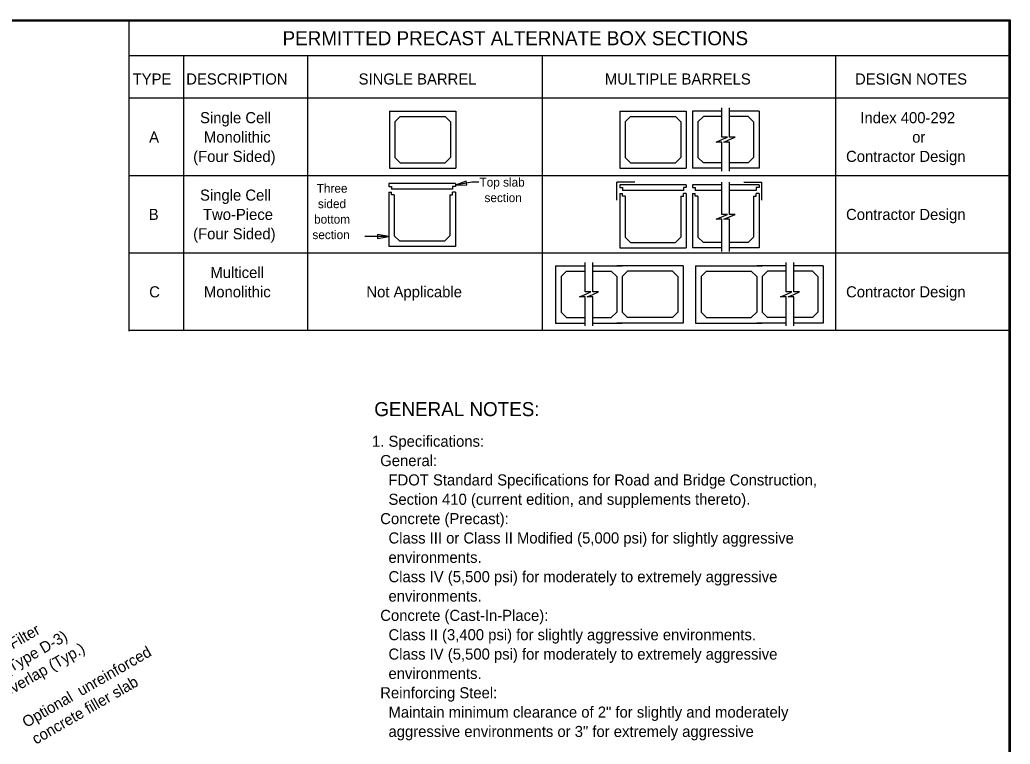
# Model space of a CAD drawing. Extents: x 0 to 123, y 0 to 78.
# Drawn here: x 69.2 to 123.2, y 38.4 to 77.9 of the extents above; entities that cross this region are included whole.
import ezdxf

# ---------------------------------------------------------------- set-up
doc = ezdxf.new("R2010")
doc.units = 0
for name, color, linetype in [('Dimension', 7, 'Continuous'), ('Miscellaneous', 7, 'Continuous'), ('Miscellaneous1', 7, 'Continuous'), ('Patterning', 7, 'Continuous'), ('SubStrConc', 7, 'Continuous'), ('TextStructures', 7, 'Continuous')]:
    doc.layers.add(name, color=color, linetype=linetype)

msp = doc.modelspace()

# ---------------------------------------------------------------- linework, layer by layer
at = {"layer": 'Dimension'}
for p, q in [((75.125, 77.856), (123.127, 77.856)), ((75.125, 77.856), (75.125, 60.919)), ((123.127, 77.856), (123.127, 60.97)), ((75.125, 75.954), (123.127, 75.954)), ((78.093, 75.954), (78.093, 60.97)), ((84.866, 75.954), (84.866, 60.97)), ((97.659, 75.954), (97.659, 60.97)), ((113.661, 75.954), (113.661, 60.97)), ((75.125, 73.642), (123.127, 73.642)), ((75.125, 69.418), (123.127, 69.418)), ((93.838, 69.053), (92.931, 68.893)), ((94.208, 69.053), (93.838, 69.053)), ((89.303, 66.08), (87.985, 66.08)), ((75.125, 65.194), (123.127, 65.194)), ((75.125, 60.97), (123.127, 60.97))]:
    msp.add_line(p, q, dxfattribs=at)
for points in [[(107.476, 69.657), (107.476, 71.235), (107.166, 71.235), (107.476, 71.37), (107.786, 71.505), (107.476, 71.505), (107.476, 73.11)], [(107.892, 69.657), (107.892, 71.235), (107.582, 71.235), (107.892, 71.37), (108.202, 71.505), (107.892, 71.505), (107.892, 73.11)], [(107.476, 65.257), (107.476, 67.021), (107.166, 67.021), (107.476, 67.156), (107.786, 67.291), (107.476, 67.291), (107.476, 69.049)], [(107.892, 65.257), (107.892, 67.021), (107.582, 67.021), (107.892, 67.156), (108.202, 67.291), (107.892, 67.291), (107.892, 69.049)], [(100.009, 61.209), (100.009, 62.787), (99.699, 62.787), (100.009, 62.922), (100.319, 63.057), (100.009, 63.057), (100.009, 64.662)], [(100.425, 61.209), (100.425, 62.787), (100.115, 62.787), (100.425, 62.922), (100.735, 63.057), (100.425, 63.057), (100.425, 64.662)], [(110.978, 61.209), (110.978, 62.787), (110.668, 62.787), (110.978, 62.922), (111.288, 63.057), (110.978, 63.057), (110.978, 64.662)], [(111.393, 61.209), (111.393, 62.787), (111.083, 62.787), (111.393, 62.922), (111.703, 63.057), (111.393, 63.057), (111.393, 64.662)]]:
    msp.add_lwpolyline(points, dxfattribs=at)
for points in [[(92.931, 68.893), (93.565, 68.898), (93.528, 69.106)], [(89.303, 66.08), (88.678, 66.186), (88.678, 65.974)]]:
    msp.add_lwpolyline(points, close=True, dxfattribs=at)
at = {"layer": 'Miscellaneous'}
for p, q in [((102.727, 69.054), (101.747, 69.054)), ((101.747, 68.074), (101.747, 69.054)), ((108.675, 69.054), (109.655, 69.054)), ((109.655, 68.074), (109.655, 69.054))]:
    msp.add_line(p, q, dxfattribs=at)
at = {"layer": 'Miscellaneous1'}
msp.add_lwpolyline([(0, 77.856), (123.127, 77.856), (123.127, 0), (0, 0)], close=True, dxfattribs=at)
at = {"layer": 'Patterning'}
msp.add_lwpolyline([(0, 77.91), (123.2, 77.91), (123.2, 0), (0, 0)], close=True, dxfattribs=at)
at = {"layer": 'SubStrConc'}
for p, q in [((89.332, 72.931), (92.96, 72.931)), ((89.332, 72.931), (89.332, 69.809)), ((89.627, 72.34), (89.923, 72.635)), ((89.923, 72.635), (92.37, 72.635)), ((92.665, 72.34), (92.37, 72.635)), ((92.96, 72.931), (92.96, 69.809)), ((101.904, 72.931), (105.532, 72.931)), ((101.904, 72.931), (101.904, 69.809)), ((102.2, 72.34), (102.495, 72.635)), ((102.495, 72.635), (104.942, 72.635)), ((105.237, 72.34), (104.942, 72.635)), ((105.532, 72.931), (105.532, 69.809)), ((105.87, 72.931), (105.87, 69.809)), ((107.476, 72.931), (105.87, 72.931)), ((106.165, 72.34), (106.46, 72.635)), ((107.476, 72.635), (106.46, 72.635)), ((109.498, 72.931), (107.892, 72.931)), ((108.907, 72.635), (107.892, 72.635)), ((109.203, 72.34), (108.907, 72.635)), ((109.498, 72.931), (109.498, 69.809)), ((89.627, 72.34), (89.627, 70.399)), ((92.665, 72.34), (92.665, 70.399)), ((102.2, 72.34), (102.2, 70.399)), ((105.237, 72.34), (105.237, 70.399)), ((106.165, 72.34), (106.165, 70.399)), ((109.203, 72.34), (109.203, 70.399)), ((89.627, 70.399), (89.923, 70.104)), ((92.665, 70.399), (92.37, 70.104)), ((102.2, 70.399), (102.495, 70.104)), ((105.237, 70.399), (104.942, 70.104)), ((106.165, 70.399), (106.46, 70.104)), ((109.203, 70.399), (108.907, 70.104)), ((89.332, 69.809), (92.96, 69.809)), ((89.923, 70.104), (92.37, 70.104)), ((101.904, 69.809), (105.532, 69.809)), ((102.495, 70.104), (104.942, 70.104)), ((107.476, 69.809), (105.87, 69.809)), ((107.476, 70.104), (106.46, 70.104)), ((108.907, 70.104), (107.892, 70.104)), ((109.498, 69.809), (107.892, 69.809)), ((92.931, 68.967), (89.303, 68.967)), ((89.303, 68.967), (89.303, 68.82)), ((89.303, 68.82), (89.451, 68.82)), ((89.451, 68.82), (89.451, 68.672)), ((92.783, 68.672), (89.451, 68.672)), ((92.783, 68.82), (92.783, 68.672)), ((92.931, 68.82), (92.783, 68.82)), ((92.931, 68.967), (92.931, 68.82)), ((105.532, 68.897), (101.904, 68.897)), ((101.904, 68.897), (101.904, 68.749)), ((101.904, 68.749), (102.052, 68.749)), ((102.052, 68.749), (102.052, 68.601)), ((105.385, 68.749), (105.385, 68.601)), ((105.532, 68.749), (105.385, 68.749)), ((105.532, 68.897), (105.532, 68.749)), ((105.87, 68.897), (105.87, 68.749)), ((107.476, 68.897), (105.87, 68.897)), ((105.87, 68.749), (106.018, 68.749)), ((106.018, 68.749), (106.018, 68.601)), ((109.498, 68.897), (107.892, 68.897)), ((109.35, 68.749), (109.35, 68.601)), ((109.498, 68.749), (109.35, 68.749)), ((109.498, 68.897), (109.498, 68.749)), ((89.303, 68.503), (89.303, 65.529)), ((89.303, 68.503), (89.451, 68.503)), ((89.451, 68.356), (89.451, 68.503)), ((89.598, 68.356), (89.451, 68.356)), ((89.598, 68.356), (89.598, 66.12)), ((92.636, 68.356), (92.636, 66.12)), ((92.636, 68.356), (92.783, 68.356)), ((92.931, 68.503), (92.783, 68.503)), ((92.783, 68.356), (92.783, 68.503)), ((92.931, 68.503), (92.931, 65.529)), ((101.904, 68.432), (101.904, 65.458)), ((101.904, 68.432), (102.052, 68.432)), ((105.385, 68.601), (102.052, 68.601)), ((102.052, 68.285), (102.052, 68.432)), ((102.2, 68.285), (102.052, 68.285)), ((102.2, 68.285), (102.2, 66.049)), ((105.237, 68.285), (105.237, 66.049)), ((105.237, 68.285), (105.385, 68.285)), ((105.532, 68.432), (105.385, 68.432)), ((105.385, 68.285), (105.385, 68.432)), ((105.532, 68.432), (105.532, 65.458)), ((105.87, 68.432), (105.87, 65.458)), ((105.87, 68.432), (106.018, 68.432)), ((107.476, 68.601), (106.018, 68.601)), ((106.018, 68.285), (106.018, 68.432)), ((106.165, 68.285), (106.018, 68.285)), ((106.165, 68.285), (106.165, 66.049)), ((109.35, 68.601), (107.892, 68.601)), ((109.203, 68.285), (109.203, 66.049)), ((109.203, 68.285), (109.35, 68.285)), ((109.498, 68.432), (109.35, 68.432)), ((109.35, 68.285), (109.35, 68.432)), ((109.498, 68.432), (109.498, 65.458)), ((89.598, 66.12), (89.894, 65.824)), ((92.636, 66.12), (92.34, 65.824)), ((102.2, 66.049), (102.495, 65.754)), ((105.237, 66.049), (104.942, 65.754)), ((106.165, 66.049), (106.46, 65.754)), ((109.203, 66.049), (108.907, 65.754)), ((92.931, 65.529), (89.303, 65.529)), ((92.34, 65.824), (89.894, 65.824)), ((101.904, 65.458), (105.532, 65.458)), ((102.495, 65.754), (104.942, 65.754)), ((107.476, 65.458), (105.87, 65.458)), ((107.476, 65.754), (106.46, 65.754)), ((108.907, 65.754), (107.892, 65.754)), ((109.498, 65.458), (107.892, 65.458)), ((98.403, 64.483), (98.403, 61.361)), ((98.403, 64.483), (100.009, 64.483)), ((100.425, 64.483), (102.031, 64.483)), ((105.364, 64.483), (101.736, 64.483)), ((105.364, 64.483), (105.364, 61.361)), ((106.039, 64.483), (109.667, 64.483)), ((106.039, 64.483), (106.039, 61.361)), ((110.978, 64.483), (109.371, 64.483)), ((112.999, 64.483), (111.393, 64.483)), ((112.999, 64.483), (112.999, 61.361)), ((98.698, 63.892), (98.993, 64.187)), ((98.698, 63.892), (98.698, 61.951)), ((98.993, 64.187), (100.009, 64.187)), ((100.425, 64.187), (101.44, 64.187)), ((101.736, 63.892), (101.44, 64.187)), ((101.736, 63.892), (101.736, 61.951)), ((102.031, 63.892), (102.326, 64.187)), ((102.031, 63.892), (102.031, 61.951)), ((104.773, 64.187), (102.326, 64.187)), ((105.068, 63.892), (104.773, 64.187)), ((105.068, 63.892), (105.068, 61.951)), ((106.334, 63.892), (106.629, 64.187)), ((106.334, 63.892), (106.334, 61.951)), ((106.629, 64.187), (109.076, 64.187)), ((109.371, 63.892), (109.076, 64.187)), ((109.371, 63.892), (109.371, 61.951)), ((109.667, 63.892), (109.962, 64.187)), ((109.667, 63.892), (109.667, 61.951)), ((110.978, 64.187), (109.962, 64.187)), ((112.409, 64.187), (111.393, 64.187)), ((112.704, 63.892), (112.409, 64.187)), ((112.704, 63.892), (112.704, 61.951)), ((98.698, 61.951), (98.993, 61.656)), ((98.993, 61.656), (100.009, 61.656)), ((100.425, 61.656), (101.44, 61.656)), ((101.736, 61.951), (101.44, 61.656)), ((102.031, 61.951), (102.326, 61.656)), ((104.773, 61.656), (102.326, 61.656)), ((105.068, 61.951), (104.773, 61.656)), ((106.334, 61.951), (106.629, 61.656)), ((106.629, 61.656), (109.076, 61.656)), ((109.371, 61.951), (109.076, 61.656)), ((109.667, 61.951), (109.962, 61.656)), ((110.978, 61.656), (109.962, 61.656)), ((112.409, 61.656), (111.393, 61.656)), ((112.704, 61.951), (112.409, 61.656)), ((98.403, 61.361), (100.009, 61.361)), ((100.425, 61.361), (102.031, 61.361)), ((105.364, 61.361), (101.736, 61.361)), ((106.039, 61.361), (109.667, 61.361)), ((110.978, 61.361), (109.371, 61.361)), ((112.999, 61.361), (111.393, 61.361))]:
    msp.add_line(p, q, dxfattribs=at)

# ---------------------------------------------------------------- texts
at = {"layer": 'Dimension'}
for s, height, p in [('TYPE', 0.6048, (75.328, 74.377)), ('DESCRIPTION', 0.6048, (78.251, 74.377)), ('SINGLE BARREL', 0.6048, (87.655, 74.377)), ('MULTIPLE BARRELS', 0.6048, (101.091, 74.377)), ('DESIGN NOTES', 0.6048, (114.735, 74.377)), ('Single Cell', 0.6048, (79.003, 72.265)), ('Index 400-292', 0.6048, (115.027, 72.265)), ('A', 0.605, (76.227, 71.209)), ('Monolithic', 0.6048, (79.216, 71.209)), ('or', 0.6048, (117.854, 71.209)), ('(Four Sided)', 0.6048, (78.628, 70.153)), ('Contractor Design', 0.6048, (114.246, 70.153)), ('Top slab', 0.48, (94.252, 68.805)), ('Single Cell', 0.6048, (79.003, 68.041)), ('Three', 0.48, (85.369, 68.474)), ('sided', 0.48, (85.434, 67.629)), ('section', 0.48, (94.523, 67.96)), ('B', 0.605, (76.207, 66.985)), ('Two-Piece', 0.6048, (79.163, 66.985)), ('Contractor Design', 0.6048, (114.246, 66.985)), ('bottom', 0.48, (85.224, 66.784)), ('(Four Sided)', 0.6048, (78.628, 65.929)), ('section', 0.48, (85.134, 65.939)), ('Multicell', 0.6048, (79.568, 63.817)), ('C', 0.605, (76.229, 62.761)), ('Monolithic', 0.6048, (79.216, 62.761)), ('Not Applicable', 0.6048, (88.078, 62.761)), ('Contractor Design', 0.6048, (114.246, 62.761)), ('1. Specifications:', 0.6048, (88.385, 54.606)), ('  General:', 0.6048, (88.385, 53.55)), ('    FDOT Standard Specifications for Road and Bridge Construction,', 0.6048, (88.385, 52.494)), ('    Section 410 (current edition, and supplements thereto).', 0.6048, (88.385, 51.438)), ('  Concrete (Precast):', 0.6048, (88.385, 50.382)), ('    Class III or Class II Modified (5,000 psi) for slightly aggressive', 0.6048, (88.385, 49.326)), ('    environments.', 0.6048, (88.385, 48.27)), ('    Class IV (5,500 psi) for moderately to extremely aggressive', 0.6048, (88.385, 47.214)), ('    environments.', 0.6048, (88.385, 46.158)), ('  Concrete (Cast-In-Place):', 0.6048, (88.385, 45.102)), ('    Class II (3,400 psi) for slightly aggressive environments.', 0.6048, (88.385, 44.046)), ('    Class IV (5,500 psi) for moderately to extremely aggressive', 0.6048, (88.385, 42.99)), ('    environments.', 0.6048, (88.385, 41.934)), ('  Reinforcing Steel:', 0.6048, (88.385, 40.878)), ('    Maintain minimum clearance of 2" for slightly and moderately', 0.6048, (88.385, 39.822)), ('    aggressive environments or 3" for extremely aggressive', 0.6048, (88.385, 38.766))]:
    msp.add_text(s, height=height, dxfattribs=at).set_placement(p)
for s, p in [('Line with Filter', (65.822, 41.835)), ('Fabric (Type D-3)', (66.35, 40.921)), ('1\'-0" overlap (Typ.)', (66.878, 40.006)), ('Optional  unreinforced', (69.525, 39.256)), ('concrete filler slab', (70.053, 38.341))]:
    msp.add_text(s, height=0.6048, rotation=30, dxfattribs=at).set_placement(p)
at = {"layer": 'TextStructures'}
for s, p in [('PERMITTED PRECAST ALTERNATE BOX SECTIONS', (83.507, 76.521)), ('GENERAL NOTES:', (88.508, 56.277))]:
    msp.add_text(s, height=0.768, dxfattribs=at).set_placement(p)

doc.saveas('drawing.dxf')
